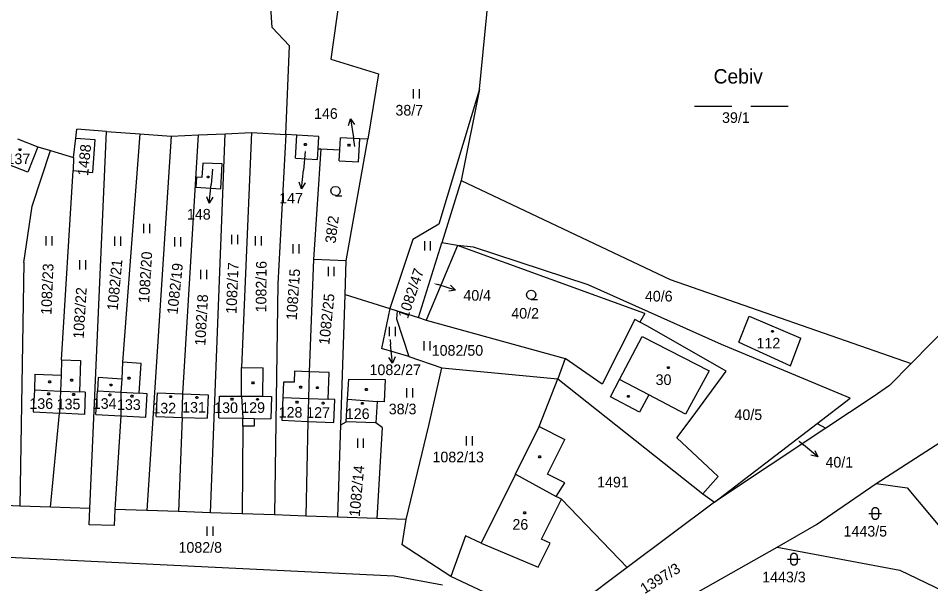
# Model space of a CAD drawing. Extents: x -852001 to -842497, y -1063614 to -1052182.
# Drawn here: x -849422.1 to -849276.2, y -1056255.4 to -1056165 of the extents above; entities that cross this region are included whole.
import ezdxf

# ---------------------------------------------------------------- set-up
doc = ezdxf.new("R2010")
doc.units = 0
for name, color, linetype in [('Default', 7, 'Continuous'), ('KN_HRANICE', 7, 'Continuous'), ('KN_KULTURY', 7, 'Continuous'), ('KN_PARCELY', 7, 'Continuous'), ('KN_SLUCKY', 7, 'Continuous')]:
    doc.layers.add(name, color=color, linetype=linetype)

# ---------------------------------------------------------------- blocks, each defined once
blk = doc.blocks.new('304')
at = {"layer": 'Default'}
blk.add_lwpolyline([(0, 0), (-0.38, 0.1), (-0.65, 0.37), (-0.75, 0.74), (-0.65, 1.11), (-0.38, 1.38), (-0.01, 1.48), (0.36, 1.38), (0.63, 1.11), (0.73, 0.73), (0.63, 0.35), (0.36, 0.08), (-0.02, -0.02), (0.98, -0.02)], dxfattribs=at)
blk = doc.blocks.new('306')
at = {"layer": 'Default'}
for p, q in [((-0.5, 1.5), (-0.5, 0)), ((0.5, 0), (0.5, 1.5))]:
    blk.add_line(p, q, dxfattribs=at)
blk = doc.blocks.new('316')
at = {"layer": 'Default'}
for points in [[(-0.5, 1.5), (-0.4, 1.79), (-0.15, 1.97), (0.16, 1.97), (0.41, 1.79), (0.51, 1.5), (0.51, 0.5), (0.41, 0.21), (0.16, 0.03), (-0.15, 0.03), (-0.4, 0.21), (-0.5, 0.5), (-0.5, 1.5)], [(-1, 1), (0.27, 1), (1, 1)]]:
    blk.add_lwpolyline(points, dxfattribs=at)
blk = doc.blocks.new('NAHRADNI_SYMBOL')
at = {"layer": 'Default'}
blk.add_lwpolyline([(0.09, 0.15), (0.18, 0), (0.09, -0.15), (-0.09, -0.15), (-0.18, 0), (-0.09, 0.15), (0.09, 0.15)], dxfattribs=at)
blk = doc.blocks.new('803')
at = {"layer": 'Default'}
for p, q in [((-7.5, 0), (-1.5, 0)), ((1.5, 0), (7.5, 0))]:
    blk.add_line(p, q, dxfattribs=at)
blk = doc.blocks.new('10292')
at = {"layer": 'Default'}
blk.add_line((0, 3), (0, 0), dxfattribs=at)
blk.add_lwpolyline([(-0.5, 2), (0, 3), (0.5, 2)], dxfattribs=at)
blk = doc.blocks.new('402')
at = {"layer": 'Default'}
blk.add_lwpolyline([(0.09, 0.15), (0.18, 0), (0.09, -0.15), (-0.09, -0.15), (-0.18, 0), (-0.09, 0.15), (0.09, 0.15)], dxfattribs=at)

msp = doc.modelspace()

# ---------------------------------------------------------------- linework, layer by layer
at = {"layer": 'KN_HRANICE'}
for p, q in [((-849381.49, -1056166.49), (-849383.75, -1056136.63)), ((-849368.45, -1056145.12), (-849372.11, -1056171.57)), ((-849348.36, -1056176.35), (-849346.5, -1056157.31)), ((-849378.74, -1056169.41), (-849381.49, -1056166.49)), ((-849379.32, -1056183.62), (-849378.74, -1056169.41)), ((-849372.11, -1056171.57), (-849364.51, -1056173.91)), ((-849364.51, -1056173.91), (-849366.23, -1056184.36)), ((-849348.36, -1056176.35), (-849354.89, -1056197.95)), ((-849348.36, -1056176.35), (-849351.28, -1056190.95)), ((-849412.91, -1056184.19), (-849412.76, -1056182.77)), ((-849408.02, -1056183.12), (-849412.76, -1056182.77)), ((-849422.22, -1056184.31), (-849418.99, -1056185.55)), ((-849413.25, -1056187.28), (-849412.91, -1056184.19)), ((-849412.91, -1056184.19), (-849409.88, -1056184.39)), ((-849410.67, -1056243.39), (-849408.02, -1056183.12)), ((-849408.02, -1056183.12), (-849402.65, -1056183.52)), ((-849402.65, -1056183.52), (-849405.42, -1056220.02)), ((-849402.65, -1056183.52), (-849397.67, -1056183.89)), ((-849397.67, -1056183.89), (-849401.57, -1056243.71)), ((-849397.67, -1056183.89), (-849393.31, -1056183.68)), ((-849395.79, -1056225.05), (-849393.31, -1056183.68)), ((-849393.31, -1056183.68), (-849389.01, -1056183.48)), ((-849391.38, -1056244.07), (-849389.01, -1056183.48)), ((-849389.01, -1056183.48), (-849384.81, -1056183.28)), ((-849384.81, -1056183.28), (-849386.41, -1056220.84)), ((-849384.81, -1056183.28), (-849379.32, -1056183.62)), ((-849379.32, -1056183.62), (-849380.59, -1056207.46)), ((-849377.59, -1056183.72), (-849379.32, -1056183.62)), ((-849377.8, -1056187.41), (-849377.59, -1056183.72)), ((-849374.05, -1056183.92), (-849377.59, -1056183.72)), ((-849374.16, -1056185.87), (-849374.05, -1056183.92)), ((-849370.69, -1056186.03), (-849370.58, -1056184.12)), ((-849367.51, -1056184.29), (-849370.58, -1056184.12)), ((-849367.72, -1056187.96), (-849367.51, -1056184.29)), ((-849366.23, -1056184.36), (-849367.51, -1056184.29)), ((-849418.99, -1056185.55), (-849420.56, -1056189.61)), ((-849418.99, -1056185.55), (-849416.94, -1056186.17)), ((-849409.88, -1056184.39), (-849410.26, -1056189.65)), ((-849369.66, -1056203.79), (-849366.23, -1056184.36)), ((-849419.86, -1056195.08), (-849416.94, -1056186.17)), ((-849416.94, -1056186.17), (-849413.25, -1056187.28)), ((-849373.73, -1056185.89), (-849374.92, -1056203.58)), ((-849374.26, -1056187.61), (-849374.16, -1056185.87)), ((-849374.16, -1056185.87), (-849373.73, -1056185.89)), ((-849373.73, -1056185.89), (-849370.69, -1056186.03)), ((-849370.79, -1056187.81), (-849370.69, -1056186.03)), ((-849420.56, -1056189.61), (-849423.72, -1056188.39)), ((-849413.25, -1056187.28), (-849413.34, -1056189.38)), ((-849392.61, -1056188.18), (-849392.73, -1056190.46)), ((-849389.53, -1056188.31), (-849392.61, -1056188.18)), ((-849389.71, -1056192.31), (-849389.53, -1056188.31)), ((-849377.8, -1056187.41), (-849374.26, -1056187.61)), ((-849370.79, -1056187.81), (-849367.72, -1056187.96)), ((-849415.18, -1056219.61), (-849413.34, -1056189.38)), ((-849413.34, -1056189.38), (-849410.26, -1056189.65)), ((-849393.59, -1056190.4), (-849393.69, -1056192.04)), ((-849392.73, -1056190.46), (-849393.59, -1056190.4)), ((-849351.28, -1056190.95), (-849354.41, -1056200.92)), ((-849351.28, -1056190.95), (-849317.91, -1056206.78)), ((-849393.69, -1056192.04), (-849389.71, -1056192.31)), ((-849421.21, -1056204.05), (-849419.86, -1056195.08)), ((-849354.89, -1056197.95), (-849359.05, -1056200.39)), ((-849359.05, -1056200.39), (-849362.71, -1056211.43)), ((-849358.1, -1056212.88), (-849354.41, -1056200.92)), ((-849351.88, -1056201.36), (-849356.9, -1056213.31)), ((-849351.88, -1056201.36), (-849354.41, -1056200.92)), ((-849321.95, -1056212.23), (-849351.88, -1056201.36)), ((-849349.3, -1056201.62), (-849351.88, -1056201.36)), ((-849331, -1056207.66), (-849349.3, -1056201.62)), ((-849421.21, -1056204.05), (-849421.86, -1056243)), ((-849374.92, -1056203.58), (-849375.6, -1056221.52)), ((-849369.66, -1056203.79), (-849374.92, -1056203.58)), ((-849369.84, -1056209.17), (-849369.66, -1056203.79)), ((-849380.59, -1056207.46), (-849381.14, -1056244.42)), ((-849309.67, -1056217.15), (-849331, -1056207.66)), ((-849317.91, -1056206.78), (-849279.38, -1056220.21)), ((-849370.54, -1056230), (-849369.84, -1056209.17)), ((-849369.84, -1056209.17), (-849362.71, -1056211.43)), ((-849362.71, -1056211.43), (-849364.05, -1056217.8)), ((-849362.71, -1056211.43), (-849361.54, -1056211.8)), ((-849361.54, -1056211.8), (-849361.64, -1056213.08)), ((-849361.54, -1056211.8), (-849358.1, -1056212.88)), ((-849361.64, -1056213.08), (-849359.68, -1056219.08)), ((-849358.1, -1056212.88), (-849356.9, -1056213.31)), ((-849356.9, -1056213.31), (-849334.65, -1056219.42)), ((-849323.51, -1056213.18), (-849328.75, -1056223.5)), ((-849322.72, -1056213.6), (-849323.51, -1056213.18)), ((-849321.95, -1056212.23), (-849322.72, -1056213.6)), ((-849306.91, -1056216.78), (-849305.24, -1056212.62)), ((-849305.24, -1056212.62), (-849297, -1056216.16)), ((-849321.49, -1056214.25), (-849322.72, -1056213.6)), ((-849308.91, -1056221.45), (-849321.49, -1056214.25)), ((-849273.04, -1056213.76), (-849279.38, -1056220.21)), ((-849298.66, -1056220.6), (-849297, -1056216.16)), ((-849359.68, -1056219.08), (-849364.05, -1056217.8)), ((-849289.11, -1056225.75), (-849309.67, -1056217.15)), ((-849306.91, -1056216.78), (-849298.66, -1056220.6)), ((-849359.68, -1056219.08), (-849354.38, -1056220.91)), ((-849415.18, -1056219.61), (-849415.26, -1056222.08)), ((-849415.18, -1056219.61), (-849412.13, -1056219.71)), ((-849412.13, -1056219.71), (-849412.3, -1056224.75)), ((-849405.42, -1056220.02), (-849405.57, -1056222.7)), ((-849402.48, -1056220.19), (-849405.42, -1056220.02)), ((-849402.75, -1056224.96), (-849402.48, -1056220.19)), ((-849334.65, -1056219.42), (-849335.86, -1056222.66)), ((-849328.75, -1056223.5), (-849334.65, -1056219.42)), ((-849279.38, -1056220.21), (-849282.8, -1056223.75)), ((-849419.43, -1056221.94), (-849419.51, -1056224.41)), ((-849419.43, -1056221.94), (-849415.26, -1056222.08)), ((-849415.26, -1056222.08), (-849415.35, -1056224.61)), ((-849386.44, -1056225.44), (-849386.41, -1056220.84)), ((-849386.41, -1056220.84), (-849382.96, -1056220.88)), ((-849382.99, -1056225.42), (-849382.96, -1056220.88)), ((-849377.94, -1056221.42), (-849378.01, -1056223.21)), ((-849375.6, -1056221.52), (-849377.94, -1056221.42)), ((-849375.6, -1056221.52), (-849375.7, -1056225.8)), ((-849372.39, -1056221.63), (-849375.6, -1056221.52)), ((-849372.57, -1056225.93), (-849372.39, -1056221.63)), ((-849356.44, -1056230.13), (-849354.38, -1056220.91)), ((-849354.38, -1056220.91), (-849335.86, -1056222.66)), ((-849314.38, -1056228.83), (-849308.91, -1056221.45)), ((-849409.34, -1056222.47), (-849409.46, -1056224.57)), ((-849405.57, -1056222.7), (-849409.34, -1056222.47)), ((-849405.57, -1056222.7), (-849405.69, -1056224.8)), ((-849379.68, -1056223.2), (-849379.78, -1056225.64)), ((-849378.01, -1056223.21), (-849379.68, -1056223.2)), ((-849369.45, -1056225.94), (-849369.26, -1056222.73)), ((-849369.26, -1056222.73), (-849363.46, -1056222.79)), ((-849363.46, -1056222.79), (-849363.6, -1056226.34)), ((-849338.84, -1056230.31), (-849335.86, -1056222.66)), ((-849335.86, -1056222.66), (-849312.67, -1056241.03)), ((-849419.51, -1056224.41), (-849419.72, -1056227.94)), ((-849415.35, -1056224.61), (-849415.49, -1056228.13)), ((-849411.41, -1056224.78), (-849412.3, -1056224.75)), ((-849411.41, -1056224.78), (-849411.53, -1056228.36)), ((-849409.68, -1056228.34), (-849409.46, -1056224.57)), ((-849405.69, -1056224.8), (-849405.72, -1056228.57)), ((-849401.5, -1056225.04), (-849402.75, -1056224.96)), ((-849401.72, -1056228.8), (-849401.5, -1056225.04)), ((-849400.03, -1056228.7), (-849399.84, -1056224.88)), ((-849399.84, -1056224.88), (-849395.79, -1056225.05)), ((-849395.88, -1056228.82), (-849395.79, -1056225.05)), ((-849395.79, -1056225.05), (-849391.74, -1056225.22)), ((-849282.8, -1056223.75), (-849285.42, -1056225.55)), ((-849391.74, -1056225.22), (-849391.9, -1056228.93)), ((-849390.04, -1056228.91), (-849389.94, -1056225.41)), ((-849389.94, -1056225.41), (-849386.44, -1056225.44)), ((-849386.44, -1056225.44), (-849386.18, -1056228.97)), ((-849382.99, -1056225.42), (-849381.64, -1056225.49)), ((-849381.64, -1056225.49), (-849381.71, -1056229.04)), ((-849379.78, -1056225.64), (-849379.94, -1056229.28)), ((-849375.7, -1056225.8), (-849375.79, -1056229.47)), ((-849371.48, -1056225.97), (-849372.57, -1056225.93)), ((-849371.66, -1056229.64), (-849371.48, -1056225.97)), ((-849369.67, -1056229.55), (-849369.45, -1056225.94)), ((-849364.72, -1056226.27), (-849364.93, -1056229.68)), ((-849363.6, -1056226.34), (-849364.72, -1056226.27)), ((-849294.36, -1056229.78), (-849289.11, -1056225.75)), ((-849285.42, -1056225.55), (-849293.01, -1056230.55)), ((-849419.72, -1056227.94), (-849415.49, -1056228.13)), ((-849416.97, -1056243.16), (-849415.49, -1056228.13)), ((-849411.53, -1056228.36), (-849415.49, -1056228.13)), ((-849409.68, -1056228.34), (-849405.72, -1056228.57)), ((-849405.72, -1056228.57), (-849406.67, -1056243.53)), ((-849405.72, -1056228.57), (-849401.72, -1056228.8)), ((-849400.03, -1056228.7), (-849395.88, -1056228.82)), ((-849395.88, -1056228.82), (-849396.47, -1056243.89)), ((-849395.88, -1056228.82), (-849391.9, -1056228.93)), ((-849390.04, -1056228.91), (-849386.18, -1056228.97)), ((-849386.21, -1056230.22), (-849386.18, -1056228.97)), ((-849384.37, -1056229), (-849384.39, -1056230.25)), ((-849384.37, -1056229), (-849381.71, -1056229.04)), ((-849379.94, -1056229.28), (-849375.79, -1056229.47)), ((-849375.79, -1056229.47), (-849376.11, -1056244.6)), ((-849375.79, -1056229.47), (-849371.66, -1056229.64)), ((-849370.54, -1056230), (-849369.67, -1056229.55)), ((-849364.93, -1056229.68), (-849369.67, -1056229.55)), ((-849316.81, -1056232.12), (-849314.38, -1056228.83)), ((-849386.21, -1056230.22), (-849386.29, -1056244.24)), ((-849384.39, -1056230.25), (-849386.21, -1056230.22)), ((-849371.04, -1056244.79), (-849370.54, -1056230)), ((-849363.91, -1056230.46), (-849364.93, -1056229.68)), ((-849363.91, -1056230.46), (-849364.79, -1056245)), ((-849360.1, -1056245.17), (-849356.44, -1056230.13)), ((-849342.6, -1056237.89), (-849338.84, -1056230.31)), ((-849338.84, -1056230.31), (-849334.72, -1056232.36)), ((-849310.77, -1056242.39), (-849294.36, -1056229.78)), ((-849293.01, -1056230.55), (-849310.77, -1056242.39)), ((-849294.36, -1056229.78), (-849293.01, -1056230.55)), ((-849337.47, -1056237.91), (-849334.72, -1056232.36)), ((-849316.81, -1056232.12), (-849310.19, -1056238.3)), ((-849284.94, -1056239.39), (-849273.87, -1056232.24)), ((-849342.6, -1056237.89), (-849348.09, -1056248.94)), ((-849334.74, -1056239.27), (-849337.47, -1056237.91)), ((-849310.19, -1056238.3), (-849312.67, -1056241.03)), ((-849336.12, -1056241.5), (-849334.74, -1056239.27)), ((-849294.48, -1056245.96), (-849284.94, -1056239.39)), ((-849284.94, -1056239.39), (-849279.99, -1056240.09)), ((-849312.67, -1056241.03), (-849310.77, -1056242.39)), ((-849279.99, -1056240.09), (-849260.83, -1056263.03)), ((-849421.86, -1056243), (-849431.74, -1056242.65)), ((-849335.27, -1056241.92), (-849336.12, -1056241.5)), ((-849335.27, -1056241.92), (-849324.78, -1056252.85)), ((-849310.77, -1056242.39), (-849324.78, -1056252.85)), ((-849416.97, -1056243.16), (-849421.86, -1056243)), ((-849410.67, -1056243.39), (-849416.97, -1056243.16)), ((-849410.76, -1056245.99), (-849410.67, -1056243.39)), ((-849406.67, -1056243.53), (-849406.76, -1056246.13)), ((-849401.57, -1056243.71), (-849406.67, -1056243.53)), ((-849396.47, -1056243.89), (-849401.57, -1056243.71)), ((-849391.38, -1056244.07), (-849396.47, -1056243.89)), ((-849386.29, -1056244.24), (-849391.38, -1056244.07)), ((-849381.14, -1056244.42), (-849386.29, -1056244.24)), ((-849376.11, -1056244.6), (-849381.14, -1056244.42)), ((-849371.04, -1056244.79), (-849376.11, -1056244.6)), ((-849364.79, -1056245), (-849371.04, -1056244.79)), ((-849360.1, -1056245.17), (-849364.79, -1056245)), ((-849360.74, -1056249.21), (-849360.1, -1056245.17)), ((-849406.76, -1056246.13), (-849410.76, -1056245.99)), ((-849300.76, -1056249.55), (-849294.48, -1056245.96)), ((-849350.61, -1056247.78), (-849352.94, -1056254.24)), ((-849348.09, -1056248.94), (-849350.61, -1056247.78)), ((-849352.94, -1056254.24), (-849360.74, -1056249.21)), ((-849321.82, -1056261.46), (-849300.76, -1056249.55)), ((-849300.76, -1056249.55), (-849281.15, -1056253.26)), ((-849424.74, -1056251.13), (-849362.03, -1056254.15)), ((-849324.78, -1056252.85), (-849332.91, -1056258.92)), ((-849362.03, -1056254.15), (-849354.27, -1056255.62)), ((-849344.89, -1056258.04), (-849352.94, -1056254.24)), ((-849281.15, -1056253.26), (-849260.83, -1056263.03))]:
    msp.add_line(p, q, dxfattribs=at)
at = {"layer": 'KN_PARCELY'}
for p, q in [((-849368.3, -1056185.51), (-849368.52, -1056184.07)), ((-849376.21, -1056186.31), (-849376.51, -1056189.3)), ((-849391.05, -1056189.16), (-849391.29, -1056191.6)), ((-849355.4, -1056207.45), (-849355.04, -1056207.56)), ((-849362.65, -1056216.42), (-849362.57, -1056217.19)), ((-849297.28, -1056232.64), (-849296.59, -1056233.22))]:
    msp.add_line(p, q, dxfattribs=at)
at = {"layer": 'KN_SLUCKY'}
for p, q in [((-849325.97, -1056222.79), (-849322.37, -1056215.9)), ((-849322.37, -1056215.9), (-849311.67, -1056221.36)), ((-849311.67, -1056221.36), (-849315.41, -1056228.3)), ((-849327.41, -1056225.56), (-849325.97, -1056222.79)), ((-849321.32, -1056225.2), (-849325.97, -1056222.79)), ((-849419.51, -1056224.41), (-849415.35, -1056224.61)), ((-849415.35, -1056224.61), (-849412.3, -1056224.75)), ((-849409.46, -1056224.57), (-849405.69, -1056224.8)), ((-849405.69, -1056224.8), (-849402.75, -1056224.96)), ((-849386.44, -1056225.44), (-849382.99, -1056225.42)), ((-849379.78, -1056225.64), (-849375.7, -1056225.8)), ((-849375.7, -1056225.8), (-849372.57, -1056225.93)), ((-849369.45, -1056225.94), (-849364.72, -1056226.27)), ((-849322.77, -1056227.98), (-849327.41, -1056225.56)), ((-849321.32, -1056225.2), (-849322.77, -1056227.98)), ((-849315.41, -1056228.3), (-849321.32, -1056225.2)), ((-849386.18, -1056228.97), (-849384.37, -1056229)), ((-849342.6, -1056237.89), (-849336.12, -1056241.5)), ((-849338.43, -1056248.28), (-849335.27, -1056241.92)), ((-849337.09, -1056248.95), (-849338.43, -1056248.28)), ((-849348.09, -1056248.94), (-849340.37, -1056252.17)), ((-849338.98, -1056252.75), (-849337.09, -1056248.95)), ((-849340.37, -1056252.17), (-849338.98, -1056252.75))]:
    msp.add_line(p, q, dxfattribs=at)

# ---------------------------------------------------------------- block references
at = {"layer": 'KN_KULTURY'}
for name, p in [('306', (-849358.48, -1056177.87)), ('803', (-849306.51, -1056179.05)), ('402', (-849376.21, -1056185.21)), ('402', (-849369.23, -1056185.32)), ('NAHRADNI_SYMBOL', (-849421.81, -1056186.03)), ('402', (-849391.74, -1056190.39)), ('304', (-849371.36, -1056193.37)), ('306', (-849401.59, -1056199.4)), ('306', (-849417.18, -1056201.37)), ('306', (-849406.2, -1056201.41)), ('306', (-849396.6, -1056201.52)), ('306', (-849387.49, -1056201.13)), ('306', (-849383.72, -1056201.36)), ('306', (-849377.7, -1056202.62)), ('306', (-849356.68, -1056202.17)), ('306', (-849411.82, -1056205.2)), ('306', (-849372.08, -1056206.24)), ('306', (-849392.47, -1056206.75)), ('304', (-849340.09, -1056209.96)), ('306', (-849362.32, -1056215.83)), ('402', (-849301.52, -1056215.06)), ('306', (-849356.75, -1056218.12)), ('402', (-849318.19, -1056220.88)), ('402', (-849417.07, -1056223.15)), ('402', (-849413.56, -1056222.87)), ('402', (-849407.26, -1056223.65)), ('402', (-849404.38, -1056222.57)), ('402', (-849384.58, -1056223.29)), ('402', (-849417.24, -1056225.07)), ('402', (-849413.25, -1056225.18)), ('402', (-849407.47, -1056225.23)), ('402', (-849376.94, -1056223.98)), ('402', (-849374.29, -1056224.07)), ('402', (-849366.45, -1056224.37)), ('306', (-849359.55, -1056225.64)), ('402', (-849403.94, -1056225.45)), ('402', (-849397.74, -1056225.52)), ('402', (-849393.56, -1056225.66)), ('402', (-849387.93, -1056225.92)), ('402', (-849383.85, -1056225.94)), ('402', (-849377.55, -1056226.41)), ('402', (-849373.36, -1056226.54)), ('402', (-849367.09, -1056226.58)), ('402', (-849324.57, -1056225.46)), ('306', (-849367.39, -1056233.69)), ('306', (-849350.01, -1056233.31)), ('402', (-849338.74, -1056235.13)), ('402', (-849341.13, -1056244.08)), ('316', (-849285.1, -1056245.18)), ('306', (-849391.43, -1056247.77)), ('316', (-849298.11, -1056252.5))]:
    msp.add_blockref(name, p, dxfattribs=at)
at = {"layer": 'KN_PARCELY'}
for p, rotation in [((-849368.52, -1056184.07), 8.651663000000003), ((-849376.51, -1056189.3), 174.29376100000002), ((-849391.29, -1056191.6), 174.408353), ((-849355.04, -1056207.56), -107.55479500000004), ((-849362.57, -1056217.19), -174.075195), ((-849296.59, -1056233.22), -130.01474100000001)]:
    msp.add_blockref('10292', p, dxfattribs=dict(at, rotation=rotation))

# ---------------------------------------------------------------- texts
for s, height, p in [('Cebiv', 2.3, (-849310.94, -1056175.45)), ('146', 1.7, (-849374.82, -1056181.1)), ('38/7', 1.7, (-849361.8, -1056180.57)), ('39/1', 1.7, (-849309.59, -1056181.75)), ('146', 0.1, (-849368.45, -1056185.51)), ('137', 1.7, (-849423.98, -1056188.34)), ('147', 0.1, (-849376.36, -1056186.31)), ('148', 0.1, (-849391.2, -1056189.16)), ('147', 1.7, (-849380.38, -1056194.63)), ('148', 1.7, (-849395.13, -1056197.2)), ('40/4', 0.1, (-849355.6, -1056207.45)), ('40/4', 1.7, (-849350.94, -1056210.17)), ('40/6', 1.7, (-849321.92, -1056210.3)), ('40/2', 1.7, (-849343.28, -1056213.04)), ('1082/27', 0.1, (-849363, -1056216.42)), ('112', 1.7, (-849304.08, -1056217.81)), ('1082/50', 1.7, (-849356, -1056218.97)), ('1082/27', 1.7, (-849365.94, -1056222.07)), ('30', 1.7, (-849320.21, -1056223.65)), ('136', 1.7, (-849420.32, -1056227.47)), ('135', 1.7, (-849415.96, -1056227.55)), ('134', 1.7, (-849410.19, -1056227.46)), ('133', 1.7, (-849406.31, -1056227.63)), ('132', 1.7, (-849400.66, -1056228.2)), ('131', 1.7, (-849395.9, -1056228.07)), ('130', 1.7, (-849390.77, -1056228.13)), ('129', 1.7, (-849386.45, -1056228.11)), ('38/3', 1.7, (-849362.87, -1056228.34)), ('128', 1.7, (-849380.47, -1056228.86)), ('127', 1.7, (-849376.06, -1056228.9)), ('126', 1.7, (-849369.73, -1056229.09)), ('40/5', 1.7, (-849307.6, -1056229.25)), ('40/1', 0.1, (-849297.46, -1056232.64)), ('1082/13', 1.7, (-849355.88, -1056236.01)), ('40/1', 1.7, (-849293.05, -1056236.85)), ('1491', 1.7, (-849329.56, -1056240.02)), ('26', 1.7, (-849343.1, -1056246.79)), ('1443/5', 1.7, (-849290.16, -1056247.88)), ('1082/8', 1.7, (-849396.48, -1056250.47)), ('1443/3', 1.7, (-849303.17, -1056255.2))]:
    msp.add_text(s, height=height, dxfattribs=at).set_placement(p)
for s, rotation, p in [('1488', 84.168, (-849410.95, -1056190.28)), ('38/2', 82.964, (-849371.38, -1056201.09)), ('1082/20', 86.459, (-849401.19, -1056210.57)), ('1082/23', 87.605, (-849416.8, -1056212.46)), ('1082/21', 84.569, (-849406.22, -1056211.81)), ('1082/19', 83.766, (-849396.65, -1056212.43)), ('1082/17', 87.491, (-849387.22, -1056212.29)), ('1082/16', 89.611, (-849382.45, -1056212.04)), ('1082/15', 86.116, (-849377.58, -1056213.32)), ('1082/47', 71.276, (-849359.83, -1056213.16)), ('1082/22', 86.517, (-849411.65, -1056216.29)), ('1082/18', 86.86, (-849392.2, -1056217.41)), ('1082/25', 83.996, (-849372.38, -1056217.3)), ('1082/14', 84.74, (-849367.52, -1056244.77)), ('1397/3', 31.742, (-849321.99, -1056257.11))]:
    msp.add_text(s, height=1.7, rotation=rotation, dxfattribs=at).set_placement(p)

doc.saveas('drawing.dxf')
